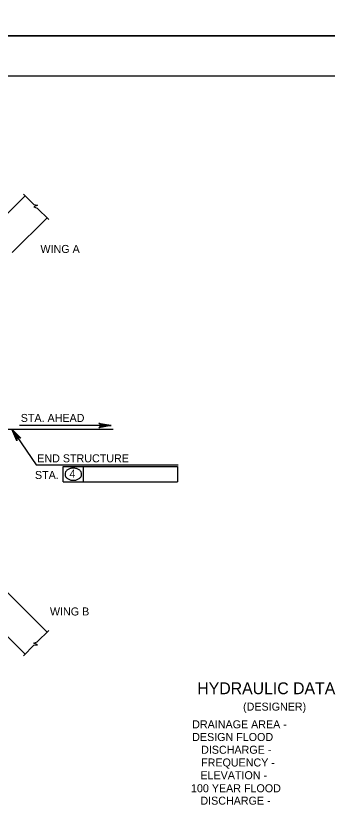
# Model space of a CAD drawing. Extents: x 638175 to 640495, y 294277 to 298435.
# Drawn here: x 638773.3 to 638889.9, y 297552.3 to 297849 of the extents above; entities that cross this region are included whole.
import ezdxf

# ---------------------------------------------------------------- set-up
doc = ezdxf.new("R2010")
doc.units = 0
for name, color, linetype in [('2', 7, 'Continuous'), ('3', 7, 'Continuous'), ('4', 7, 'Continuous'), ('PLT-BNDY', 7, 'Continuous')]:
    doc.layers.add(name, color=color, linetype=linetype)

msp = doc.modelspace()

# ---------------------------------------------------------------- linework, layer by layer
at = {"layer": '2'}
for p, q in [((638475.46, 297826.46), (639261.46, 297826.46)), ((638758.92, 297763.65), (638776.79, 297781.51)), ((638772, 297760.26), (638785.02, 297773.28)), ((638769.69, 297633.23), (638785.02, 297617.9)), ((638758.92, 297627.53), (638776.79, 297609.66))]:
    msp.add_line(p, q, dxfattribs=at)
at = {"layer": '3'}
for p, q in [((638780.12, 297778.19), (638776.21, 297782.09)), ((638781.47, 297778.02), (638780.08, 297777.33)), ((638780.08, 297777.33), (638781.39, 297776.91)), ((638780.12, 297778.19), (638781.47, 297778.02)), ((638785.66, 297772.64), (638781.39, 297776.91)), ((638785.66, 297618.53), (638781.39, 297614.26)), ((638780.08, 297613.85), (638781.39, 297614.26)), ((638781.47, 297613.15), (638780.08, 297613.85)), ((638780.12, 297612.99), (638776.21, 297609.08)), ((638780.12, 297612.99), (638781.47, 297613.15))]:
    msp.add_line(p, q, dxfattribs=at)
at = {"layer": '4'}
for p, q in [((638524.79, 297694.01), (638809.81, 297694.01)), ((638771.82, 297694.01), (638780.99, 297680.67)), ((638809.04, 297695.42), (638774.69, 297695.42)), ((638780.99, 297680.67), (638834.18, 297680.67)), ((638791.09, 297680.06), (638798.67, 297680.06)), ((638791.09, 297674.29), (638791.09, 297680.06)), ((638798.67, 297674.29), (638798.67, 297680.06)), ((638798.67, 297680.06), (638833.85, 297680.06)), ((638833.85, 297680.06), (638833.85, 297674.29)), ((638791.09, 297674.29), (638833.85, 297674.29))]:
    msp.add_line(p, q, dxfattribs=at)
for points in [[(638771.82, 297694.01), (638775.18, 297690.67), (638774.77, 297690.82), (638774.41, 297690.8), (638774.12, 297690.67), (638773.89, 297690.45), (638773.74, 297690.12), (638773.74, 297689.68), (638771.82, 297694.01), (638773.74, 297690.12), (638773.89, 297690.45), (638771.82, 297694.01), (638774.12, 297690.67), (638774.41, 297690.8), (638771.82, 297694.01), (638774.77, 297690.82)], [(638809.04, 297695.42), (638804.38, 297694.55), (638804.74, 297694.79), (638804.93, 297695.11), (638804.98, 297695.42), (638804.93, 297695.73), (638804.74, 297696.04), (638804.38, 297696.29), (638809.04, 297695.42), (638804.74, 297696.04), (638804.93, 297695.73), (638809.04, 297695.42), (638804.98, 297695.42), (638804.93, 297695.11), (638809.04, 297695.42), (638804.74, 297694.79)]]:
    msp.add_lwpolyline(points, dxfattribs=at)
for centre, radius, start, end in [((638794.14, 297676.75), 2.49, 126.3544, 150.6308), ((638794.59, 297676.15), 3.23, 106.9552, 126.3544), ((638794.87, 297675.2), 4.22, 90, 106.9552), ((638794.87, 297675.2), 4.22, 73.0448, 90), ((638795.16, 297676.15), 3.23, 53.6456, 73.0448), ((638795.6, 297676.75), 2.49, 29.3692, 53.6456), ((638793.47, 297677.13), 1.71, 150.6308, 180), ((638793.47, 297677.13), 1.71, 180, 209.3692), ((638794.14, 297677.51), 2.49, 209.3692, 233.6456), ((638795.6, 297677.51), 2.49, 306.3544, 330.6308), ((638796.28, 297677.13), 1.71, 0, 29.3692), ((638796.28, 297677.13), 1.71, 330.6308, 0), ((638794.59, 297678.11), 3.23, 233.6456, 253.0448), ((638794.87, 297679.05), 4.22, 253.0448, 270), ((638794.87, 297679.05), 4.22, 270, 286.9552), ((638795.16, 297678.11), 3.23, 286.9552, 306.3544)]:
    msp.add_arc(centre, radius, start, end, dxfattribs=at)
at = {"layer": 'PLT-BNDY'}
for points in [[(638435.46, 298435.46), (639276.46, 298435.46), (639276.46, 297841.46), (638435.46, 297841.46)], [(638435.46, 297841.46), (639276.46, 297841.46), (639276.46, 297247.46), (638435.46, 297247.46)]]:
    msp.add_lwpolyline(points, close=True, dxfattribs=at)

# ---------------------------------------------------------------- texts
at = {"layer": '4'}
for s, height, p in [('WING A', 3, (638782.56, 297760.07)), ('STA. AHEAD', 3, (638775.18, 297696.72)), ('END STRUCTURE', 3, (638781.37, 297681.58)), ('4', 3, (638793.42, 297675.78)), ('STA.', 3, (638780.5, 297675.34)), ('WING B', 3, (638786.12, 297624.17)), ('HYDRAULIC DATA', 4.4292, (638841.31, 297594.66)), ('(DESIGNER)', 3, (638858.45, 297588.5)), ('DRAINAGE AREA - ', 3, (638839.39, 297581.87)), ('DESIGN FLOOD  ', 3, (638839.39, 297577.12)), ('   DISCHARGE - ', 3, (638839.39, 297572.33)), ('   FREQUENCY - ', 3, (638839.39, 297567.56)), ('   ELEVATION - ', 3, (638839.12, 297562.79)), ('100 YEAR FLOOD', 3, (638838.94, 297557.9)), ('   DISCHARGE - ', 3, (638839.12, 297553.25))]:
    msp.add_text(s, height=height, dxfattribs=at).set_placement(p)

doc.saveas('drawing.dxf')
